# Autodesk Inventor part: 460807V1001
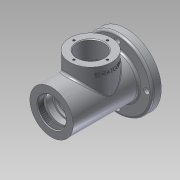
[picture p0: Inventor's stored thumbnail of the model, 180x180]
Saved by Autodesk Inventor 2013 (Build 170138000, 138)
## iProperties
Created: 2016-08
Part Number: 460807V1001
Material: 알루미늄 6061
Document SubType Name: Modeling
Designer: Administrator
Density: 2.71 g/cm^3
Mass: 740.354 g
Surface Area: 606.965 cm^2
Volume: 273.193 cm^3
Author: Administrator
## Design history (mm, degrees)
sketch "스케치2"
  geometry: L1 (0, 31)-(0, 0); L2 (9, 0)-(9, 24); L3 (9, 24)-(12, 24); L4 (12, 24)-(12, 20); L5 (12, 20)-(21, 20); L6 (21, 20)-(21, 17.5); L7 (21, 17.5)-(24.25, 17.5); L8 (24.25, 17.5)-(24.25, 18.5); L9 (24.25, 18.5)-(26, 18.5); L10 (26, 18.5)-(26, 17.5); L11 (26, 17.5)-(37, 17.5); L12 (37, 17.5)-(37, 26); L13 (37, 26)-(75, 26); L14 (75, 26)-(75, 17.5); L15 (86, 16.5)-(86, 10); L16 (86, 10)-(88.7, 10); L17 (110, 21)-(110, 31); L18 (110, 31)-(107, 31); L19 (107, 31)-(107, 50); L20 (107, 50)-(94, 50); L21 (94, 50)-(94, 31); L22 (94, 31)-(0, 31); L23 (0, 0)-(115, 0); L24 (88.7, 10)-(88.7, 12.5); L25 (88.7, 12.5)-(96, 12.5); L26 (96, 12.5)-(96, 16); L27 (96, 16)-(110, 21); L28 (75, 17.5)-(81, 17.5); L29 (81, 17.5)-(81, 16.5); L30 (81, 16.5)-(86, 16.5); L31 (56, 26)-(56, 0)
  constraints: 62 end point, 16 parallel, 9 perpendicular, 2 point on line, 1 midpoint, 1 vertical
  dimensions: "d0" = 62 diameter of L22 L23; "d3" = 40 diameter of L5 L23; "d4" = 48 diameter of L3 L23; "d5" = 3 distance between parallel lines of L4 L2; "d6" = 12 distance between parallel lines of L1 L4; "d7" = 21 distance between parallel lines of L1 L6; "d9" = 26 distance between parallel lines of L1 L10; "d12" = 37 diameter of L9 L23; "d13" = 35 diameter of L7 L23; "d14" = 1.75 distance between parallel lines of L10 L8; "d15" = 35 diameter of L11 L23; "d18" = 52 diameter of L13 L23; "d20" = 60 distance between parallel lines of L15 L10; "d23" = 14 distance from line of L17 L25.end; "d24" = 2.7 distance of L15.end L16.end; "d25" = 7.3 distance of L24.end L25.end; "d27" = 20 diameter of L16 L23; "d28" = 25 diameter of L25 L23; "d29" = 32 diameter of L26.end L23; "d30" = 42 diameter of L17.start L23; "d31" = 3 distance between parallel lines of L17 L19; "d32" = 13 distance between parallel lines of L19 L21; "d33" = 100 diameter of L20 L23; "d34" = 62 diameter of L18 L23; "d35" = 115 distance of L1.end L23.end; "d36" = 33 diameter of L30 L23; "d37" = 5 distance of L29.end L15.start; "d38" = 35 diameter of L28 L23; "d76" = 56 distance between parallel lines of L1 L31; "d77" = 19 distance between parallel lines of L12 L31; "d78" = 38 distance between parallel lines of L12 L14
revolve "회전1" sketch "스케치2" stored, may be unused: angle "d41" = 90 deg
sketch "스케치3"
  geometry: C1 r 31 at (0, 0) reference; C2 r 21 at (0, 0)
  constraints: 1 centre point, 1 coincident
  dimensions: "d42" = 42 diameter of C2
hole "구멍1" sketch "스케치3" at (0, 0) diameter "d44" = 40.376; stored, may be unused: countersink angle "d48" = 90 deg, drill point angle "d50" = 118 deg; dims "d45" = 6, "d46" = 4, "d47" = 2, "d49" = 9
fillet "모깎기1" dims "d51" = 3
chamfer "모따기1" distance "d52" = 1; stored, may be unused: second distance "d53" = 2, angle "d54" = 30 deg
fillet "모깎기2" dims "d55" = 3
chamfer "모따기2" distance "d56" = 0.7; stored, may be unused: second distance "d57" = 2, angle "d58" = 30 deg
fillet "모깎기3" dims "d59" = 0.3
fillet "모깎기4" dims "d60" = 0.3
chamfer "모따기3" distance "d61" = 1; stored, may be unused: second distance "d62" = 2, angle "d63" = 30 deg
chamfer "모따기4" distance "d64" = 1; stored, may be unused: second distance "d65" = 2, angle "d66" = 30 deg
node "작업 평면1"
sketch "스케치4"
  geometry: L1 (31, 0)-(-31, 0) reference; C1 r 30 at (0, 56); 2 further points
  constraints: 1 centre point, 1 midpoint, 1 vertical alignment
  dimensions: "d68" = 56 distance from line of L1 C1.centre; "d69" = 60 diameter of C1
extrude "돌출1" join sketch "스케치4" stored distance "d70" = 10; taper "d71" = 0 deg
sketch "스케치5"
  geometry: C1 r 30 at (0, 0) reference; C2 r 19 at (0, 0); 1 further point
  constraints: 1 centre point, 1 coincident
  dimensions: "d72" = 38 diameter of C2
extrude "돌출2" cut sketch "스케치5" stored distance "d74" = 10; taper "d75" = 0 deg
sketch "스케치6" dims "d79" = 48
  geometry: C1 r 19 at (0, 0) reference; C2 r 30 at (0, 0) reference; C3 r 2 at (0, 24); 2 further points
  constraints: 2 vertical alignment, 1 centre point, 1 coincident, 2 other
  dimensions: "d81" = 4 diameter of C3
hole "구멍2" sketch "스케치6" at (0, 24) diameter "d82" = 3.242; stored, may be unused: countersink angle "d86" = 90 deg, drill point angle "d88" = 118 deg; dims "d83" = 8, "d84" = 4, "d85" = 2, "d87" = 10
chamfer "모따기5" distance "d92" = 1; stored, may be unused: second distance "d93" = 2, angle "d94" = 30 deg
fillet "모깎기5" dims "d95" = 3
fillet "모깎기6" dims "d96" = 3
node "작업 평면2"
sketch "스케치7"
  geometry: L1 (26, 49)-(86, 49) reference; L2 (35.261, 42.002)-(76.739, 42.002); L3 (76.739, 42.002)-(76.739, 35.998); L4 (76.739, 35.998)-(35.261, 35.998); L5 (35.261, 35.998)-(35.261, 42.002); L6 (35.261, 39)-(76.739, 39); L7 (56, 42.002)-(56, 35.998); 1 further point
  constraints: 4 end point, 4 midpoint, 2 other
  dimensions: "d98" = 56 distance from line of point (0, 0) L7; "d99" = 10 distance between parallel lines of L1 L6
feature "엠보싱1" sketch "스케치7" dims "d100" = 0.5, "d101" = 0
sketch "스케치8" dims "d102" = 83
  geometry: C1 r 31 at (0, 0) reference; C2 r 50 at (0, 0) reference; C3 r 4 at (0, 41.5); 1 further point
  constraints: 2 vertical alignment, 1 centre point, 1 coincident, 2 other
  dimensions: "d104" = 8 diameter of C3
extrude "돌출3" cut sketch "스케치8" stored distance "d105" = 10; taper "d106" = 0 deg
fillet "모깎기7" dims "d110" = 3
node "솔리드1"
pattern_circular "원형 패턴1" dims angle "d90" = 360 deg
pattern_circular "원형 패턴2" dims angle "d108" = 360 deg
other parameters: "d67" = 49, "d97" = 58
